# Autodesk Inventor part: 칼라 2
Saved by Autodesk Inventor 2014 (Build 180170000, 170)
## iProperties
Created: 2026-04
Part Number: 칼라 2
Material: 강철, 연강
Document SubType Name: Modeling
Designer: dg
Density: 7.86 g/cm^3
Appearance: 강철
Author: jhkim
Creation Date: 2026-03-27
Sending System: Autodesk Inventor 2026
Preprocessor: ST-DEVELOPER v20.1
Author: dg
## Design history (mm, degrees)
node "칼라 21"
node "솔리드1"
node "기준1"
